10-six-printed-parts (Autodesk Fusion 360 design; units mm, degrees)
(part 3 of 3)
work_plane "WorkPlane3" AlongDistance -29 (= "hubFace - adapterThickness") ExtraOffset 0
sketch "F Shaft Clearance sketch" plane through (-20.5061, -20.5061, 0) normal (0.7071, 0.7071, 0) x axis (0, 0, 1)
  circle C1 centre (0, 0) radius 4.25
  dimension "d978" diameter C1 = 8.5 (= "shaftClearance")
extrude "Extrude3" cut sketch "F Shaft Clearance sketch" along normal blind 6 (= "adapterThickness")
work_plane "WorkPlane4" AlongDistance -29 (= "hubFace - adapterThickness") ExtraOffset 0
sketch "F Mount Holes" plane through (-20.5061, -20.5061, 0) normal (0.7071, 0.7071, 0) x axis (0, 0, 1)
  circle C1 centre (22.6274, 22.6274) radius 2.15
  circle C2 centre (-22.6274, 22.6274) radius 2.15
  circle C3 centre (-22.6274, -22.6274) radius 2.15
  circle C4 centre (22.6274, -22.6274) radius 2.15
  point P1 (0, 0)
  point P2 (22.6274, 22.6274)
  point P3 (-22.6274, 22.6274)
  point P4 (-22.6274, -22.6274)
  point P5 (22.6274, -22.6274)
  dimension "d983" distance P1 P2 = 22.6274 (= "abs(mountCircle / ( 2 * sqrt(2) ))")
  dimension "d984" distance P1 P2 = 22.6274 (= "abs(mountCircle / ( 2 * sqrt(2) ))")
  dimension "d985" diameter C1 = 4.3 (= "m4Clearance")
  dimension "d986" distance P1 P3 = 22.6274 (= "abs(-mountCircle / ( 2 * sqrt(2) ))")
  dimension "d987" distance P1 P3 = 22.6274 (= "abs(mountCircle / ( 2 * sqrt(2) ))")
  dimension "d988" diameter C2 = 4.3 (= "m4Clearance")
  dimension "d989" distance P1 P4 = 22.6274 (= "abs(-mountCircle / ( 2 * sqrt(2) ))")
  dimension "d990" distance P1 P4 = 22.6274 (= "abs(-mountCircle / ( 2 * sqrt(2) ))")
  dimension "d991" diameter C3 = 4.3 (= "m4Clearance")
  dimension "d992" distance P1 P5 = 22.6274 (= "abs(mountCircle / ( 2 * sqrt(2) ))")
  dimension "d993" distance P1 P5 = 22.6274 (= "abs(-mountCircle / ( 2 * sqrt(2) ))")
  dimension "d994" diameter C4 = 4.3 (= "m4Clearance")
extrude "Extrude4" cut sketch "F Mount Holes" along normal blind 6 (= "adapterThickness")
sketch "F Compression Sleeve Holes" plane through (-20.5061, -20.5061, 0) normal (0.7071, 0.7071, 0) x axis (0, 0, 1)
  line L1 (11.3137, 0) -> (0, 0)
  line L2 (0, 11.3137) -> (0, 0)
  line L3 (-11.3137, 0) -> (0, 0)
  line L4 (0, -11.3137) -> (0, 0)
  circle C1 centre (11.3137, 0) radius 4.1
  circle C2 centre (0, 11.3137) radius 4.1
  circle C3 centre (-11.3137, 0) radius 4.1
  circle C4 centre (0, -11.3137) radius 4.1
  point P1 (0, 0)
  point P2 (11.3137, 0)
  point P3 (0, 11.3137)
  point P5 (0, -11.3137)
  horizontal L1
  vertical L2
  horizontal L3
  vertical L4
  dimension "d997" distance P1 P2 = 11.3137 (= "abs(hubHoleSpacing / sqrt(2))")
  dimension "d998" diameter C1 = 8.2 (= "sleeveOD + sleeveAllowance")
  dimension "d999" distance P1 P3 = 11.3137 (= "abs(hubHoleSpacing / sqrt(2))")
  dimension "d1000" diameter C2 = 8.2 (= "sleeveOD + sleeveAllowance")
  dimension "d59" = 150 (= "bodyWidth")
  dimension "d1002" diameter C3 = 8.2 (= "sleeveOD + sleeveAllowance")
  dimension "d1003" distance P1 P5 = 11.3137 (= "abs(-hubHoleSpacing / sqrt(2))")
  dimension "d1004" diameter C4 = 8.2 (= "sleeveOD + sleeveAllowance")
  dimension "d1001" distance = 11.3137 (= "abs(-hubHoleSpacing / sqrt(2))")
extrude "Extrude5" cut sketch "F Compression Sleeve Holes" profile of C1 C2 C3 C4 along normal blind 6 (= "adapterThickness")
chamfer "Chamfer1" distance 0.4 (= "entryChamfer")
chamfer "Chamfer2" distance 0.3 (= "bedRelief")
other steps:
base_feature "Base Feature1" bodies "A Housing print"
base_feature "Base Feature1" bodies "B Moving Body print"
create_component "CreateComponent1"
reparent_decal "ReparentDecal1"
remove_body "RemoveBody1"
create_component "CreateComponent2"
reparent_decal "ReparentDecal2"
remove_body "RemoveBody2"
create_component "CreateComponent3"
create_component "CreateComponent4"
create_component "CreateComponent5"
create_component "CreateComponent6"
named bodies: "A Housing print", "B Moving Body print"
